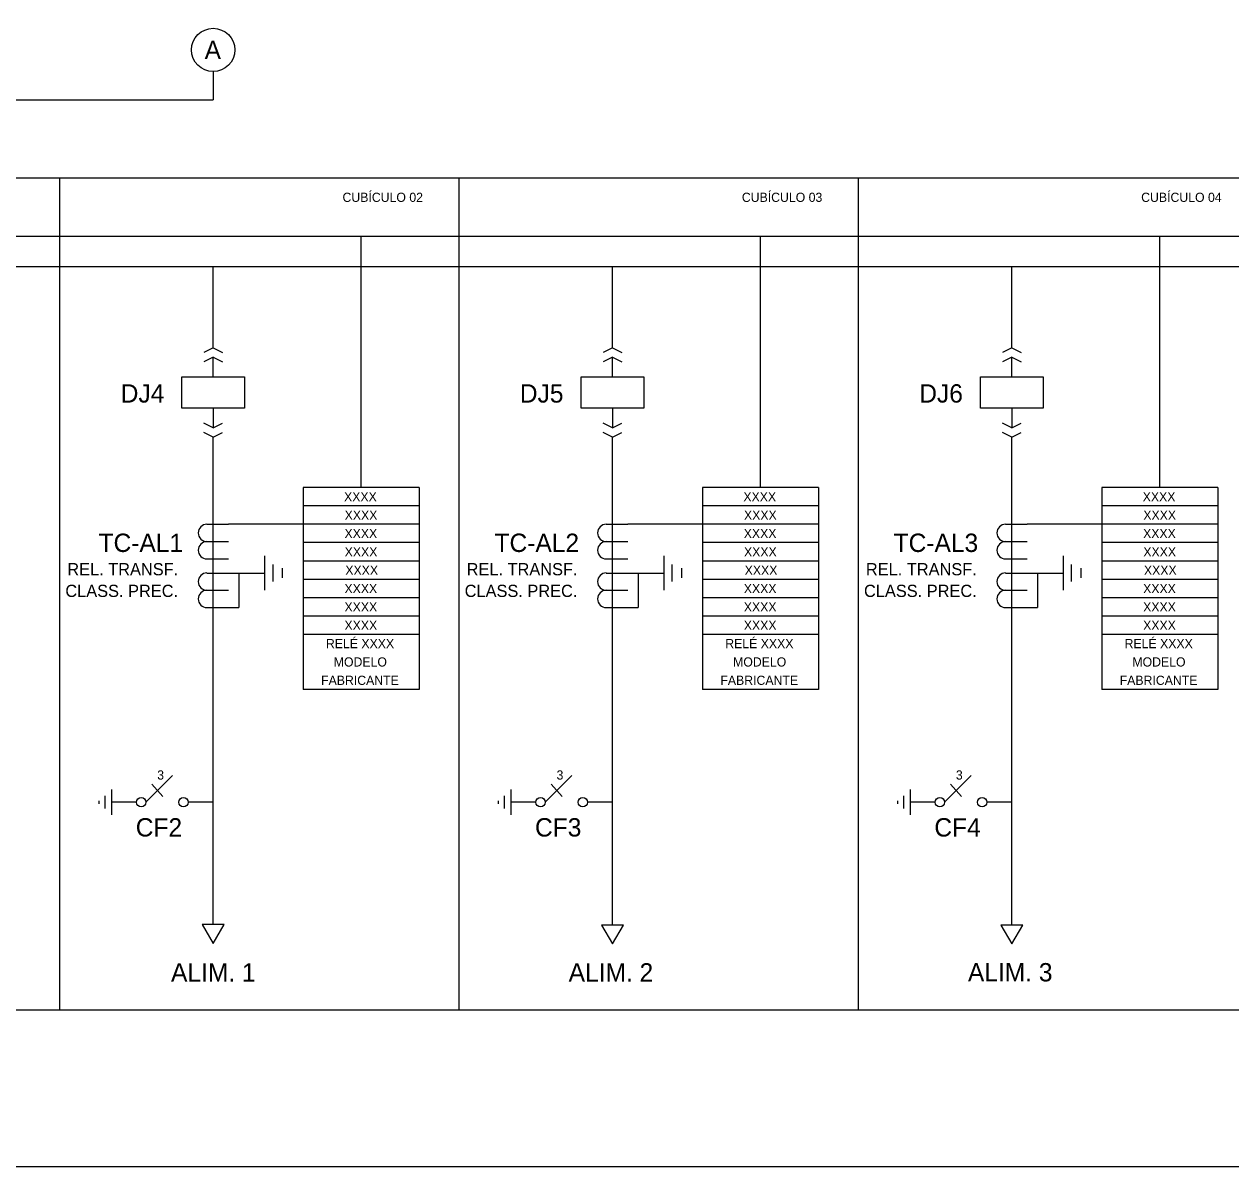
# Model space of a CAD drawing. Extents: x 563 to 1404, y 358 to 952.
# Drawn here: x 768.9 to 966.2, y 561.3 to 748.2 of the extents above; entities that cross this region are included whole.
import ezdxf

# ---------------------------------------------------------------- set-up
doc = ezdxf.new("R2010")
doc.units = 0
doc.layers.add('13', color=7, linetype='Continuous')
doc.layers.add('New Level (0)', color=7, linetype='Continuous')

msp = doc.modelspace()

# ---------------------------------------------------------------- linework, layer by layer
for p, q in [((799.81, 740.38), (799.81, 735.75)), ((650.86, 735.75), (799.81, 735.75)), ((1296.89, 722.95), (622.37, 722.95)), ((774.67, 722.95), (774.67, 586.96)), ((774.67, 722.95), (774.67, 586.96)), ((839.94, 722.95), (839.94, 586.96)), ((839.94, 722.95), (839.94, 586.96)), ((905.22, 722.95), (905.22, 586.96)), ((905.22, 722.95), (905.22, 586.96)), ((1280.96, 713.45), (705.72, 713.45)), ((824.01, 672.38), (824.01, 713.45)), ((889.29, 672.38), (889.29, 713.45)), ((954.57, 672.38), (954.57, 713.45)), ((1256.75, 708.46), (681.52, 708.46)), ((799.81, 695.25), (799.81, 708.46)), ((799.81, 695.25), (799.81, 708.46)), ((865.09, 695.25), (865.09, 708.46)), ((865.09, 695.25), (865.09, 708.46)), ((930.37, 695.25), (930.37, 708.46)), ((930.37, 695.25), (930.37, 708.46)), ((799.81, 690.5), (799.81, 693.73)), ((799.81, 690.5), (799.81, 693.73)), ((865.09, 690.5), (865.09, 693.73)), ((865.09, 690.5), (865.09, 693.73)), ((930.37, 690.5), (930.37, 693.73)), ((930.37, 690.5), (930.37, 693.73)), ((794.69, 685.38), (794.69, 690.5)), ((794.69, 690.5), (804.93, 690.5)), ((804.93, 690.5), (804.93, 685.38)), ((859.97, 685.38), (859.97, 690.5)), ((859.97, 690.5), (870.21, 690.5)), ((870.21, 690.5), (870.21, 685.38)), ((925.24, 685.38), (925.24, 690.5)), ((925.24, 690.5), (935.49, 690.5)), ((935.49, 690.5), (935.49, 685.38)), ((804.93, 685.38), (794.69, 685.38)), ((799.81, 685.38), (799.81, 682.16)), ((870.21, 685.38), (859.97, 685.38)), ((865.09, 685.38), (865.09, 682.16)), ((935.49, 685.38), (925.24, 685.38)), ((930.37, 685.38), (930.37, 682.16)), ((799.81, 600.97), (799.81, 680.63)), ((865.09, 600.87), (865.09, 680.63)), ((930.37, 600.87), (930.37, 680.63)), ((833.5, 672.38), (814.52, 672.38)), ((814.52, 672.38), (814.52, 639.38)), ((833.5, 672.38), (833.5, 639.38)), ((898.78, 672.38), (879.8, 672.38)), ((879.8, 672.38), (879.8, 639.38)), ((898.78, 672.38), (898.78, 639.38)), ((964.06, 672.38), (945.08, 672.38)), ((945.08, 672.38), (945.08, 639.38)), ((964.06, 672.38), (964.06, 639.38)), ((833.5, 669.38), (814.52, 669.38)), ((898.78, 669.38), (879.8, 669.38)), ((964.06, 669.38), (945.08, 669.38)), ((798.79, 666.38), (802.32, 666.38)), ((814.52, 666.38), (802.32, 666.38)), ((833.5, 666.38), (814.52, 666.38)), ((864.06, 666.38), (867.6, 666.38)), ((879.8, 666.38), (867.6, 666.38)), ((898.78, 666.38), (879.8, 666.38)), ((929.34, 666.38), (932.88, 666.38)), ((945.08, 666.38), (932.88, 666.38)), ((964.06, 666.38), (945.08, 666.38)), ((798.79, 663.55), (802.32, 663.55)), ((833.5, 663.38), (814.52, 663.38)), ((864.06, 663.55), (867.6, 663.55)), ((898.78, 663.38), (879.8, 663.38)), ((929.34, 663.55), (932.88, 663.55)), ((964.06, 663.38), (945.08, 663.38)), ((808.19, 661.21), (808.19, 655.63)), ((873.47, 661.21), (873.47, 655.63)), ((938.74, 661.21), (938.74, 655.63)), ((798.79, 660.72), (802.32, 660.72)), ((809.59, 657.02), (809.59, 659.82)), ((811.07, 659.2), (811.07, 657.64)), ((833.5, 660.38), (814.52, 660.38)), ((864.06, 660.72), (867.6, 660.72)), ((874.86, 657.02), (874.86, 659.82)), ((876.34, 659.2), (876.34, 657.64)), ((898.78, 660.38), (879.8, 660.38)), ((929.34, 660.72), (932.88, 660.72)), ((940.14, 657.02), (940.14, 659.82)), ((941.62, 659.2), (941.62, 657.64)), ((964.06, 660.38), (945.08, 660.38)), ((798.79, 658.42), (802.32, 658.42)), ((799.81, 658.42), (808.19, 658.42)), ((833.5, 657.38), (814.52, 657.38)), ((864.06, 658.42), (867.6, 658.42)), ((865.09, 658.42), (873.47, 658.42)), ((898.78, 657.38), (879.8, 657.38)), ((929.34, 658.42), (932.88, 658.42)), ((930.37, 658.42), (938.74, 658.42)), ((964.06, 657.38), (945.08, 657.38)), ((798.79, 655.59), (802.32, 655.59)), ((864.06, 655.59), (867.6, 655.59)), ((929.34, 655.59), (932.88, 655.59)), ((833.5, 654.38), (814.52, 654.38)), ((833.5, 654.38), (814.52, 654.38)), ((898.78, 654.38), (879.8, 654.38)), ((898.78, 654.38), (879.8, 654.38)), ((964.06, 654.38), (945.08, 654.38)), ((964.06, 654.38), (945.08, 654.38)), ((798.79, 652.76), (804, 652.76)), ((833.5, 651.38), (814.52, 651.38)), ((864.06, 652.76), (869.28, 652.76)), ((898.78, 651.38), (879.8, 651.38)), ((929.34, 652.76), (934.55, 652.76)), ((964.06, 651.38), (945.08, 651.38)), ((833.5, 648.38), (814.52, 648.38)), ((898.78, 648.38), (879.8, 648.38)), ((964.06, 648.38), (945.08, 648.38)), ((833.5, 639.38), (814.52, 639.38)), ((898.78, 639.38), (879.8, 639.38)), ((964.06, 639.38), (945.08, 639.38)), ((793.15, 625.29), (788.81, 620.95)), ((789.8, 623.9), (791.6, 621.88)), ((858.43, 625.29), (854.09, 620.95)), ((855.08, 623.9), (856.87, 621.88)), ((923.7, 625.29), (919.36, 620.95)), ((920.35, 623.9), (922.15, 621.88)), ((782.15, 619.93), (782.15, 621.98)), ((783.18, 623), (783.18, 618.91)), ((847.43, 619.93), (847.43, 621.98)), ((848.45, 623), (848.45, 618.91)), ((912.71, 619.93), (912.71, 621.98)), ((913.73, 623), (913.73, 618.91)), ((781.14, 621.19), (781.14, 620.66)), ((787.27, 620.95), (783.18, 620.95)), ((799.81, 620.95), (795.71, 620.95)), ((846.41, 621.19), (846.41, 620.66)), ((852.55, 620.95), (848.45, 620.95)), ((865.09, 620.95), (860.99, 620.95)), ((911.69, 621.19), (911.69, 620.66)), ((917.83, 620.95), (913.73, 620.95)), ((930.37, 620.95), (926.27, 620.95)), ((801.62, 600.97), (798, 600.97)), ((798, 600.97), (799.81, 597.87)), ((801.62, 600.97), (798, 600.97)), ((799.81, 597.87), (801.62, 600.97)), ((866.9, 600.87), (863.28, 600.87)), ((863.28, 600.87), (865.09, 597.77)), ((866.9, 600.87), (863.28, 600.87)), ((865.09, 597.77), (866.9, 600.87)), ((932.18, 600.87), (928.56, 600.87)), ((932.18, 600.87), (928.56, 600.87)), ((928.56, 600.87), (930.37, 597.77)), ((930.37, 597.77), (932.18, 600.87)), ((1296.89, 586.96), (622.37, 586.96))]:
    msp.add_line(p, q)
for centre in [(788.04, 620.95), (794.95, 620.95), (853.32, 620.95), (860.22, 620.95), (918.6, 620.95), (925.5, 620.95)]:
    msp.add_circle(centre, 0.768)
for centre in [(798.79, 664.97), (864.06, 664.97), (929.34, 664.97), (798.79, 662.14), (864.06, 662.14), (929.34, 662.14), (798.79, 657.01), (864.06, 657.01), (929.34, 657.01), (798.79, 654.18), (864.06, 654.18), (929.34, 654.18)]:
    msp.add_arc(centre, 1.42, 90, 270)
at = {"layer": '13'}
for p, q in [((799.81, 695.25), (798.28, 694.49)), ((799.81, 695.25), (801.34, 694.49)), ((865.09, 695.25), (863.56, 694.49)), ((865.09, 695.25), (866.61, 694.49)), ((930.37, 695.25), (928.84, 694.49)), ((930.37, 695.25), (931.89, 694.49)), ((799.81, 693.73), (798.28, 692.97)), ((799.81, 693.73), (801.34, 692.97)), ((865.09, 693.73), (863.56, 692.97)), ((865.09, 693.73), (866.61, 692.97)), ((930.37, 693.73), (928.84, 692.97)), ((930.37, 693.73), (931.89, 692.97)), ((799.81, 682.16), (798.28, 682.92)), ((799.81, 682.16), (801.34, 682.92)), ((865.09, 682.16), (863.56, 682.92)), ((865.09, 682.16), (866.61, 682.92)), ((930.37, 682.16), (928.84, 682.92)), ((930.37, 682.16), (931.89, 682.92)), ((799.81, 680.63), (798.28, 681.4)), ((799.81, 680.63), (801.34, 681.4)), ((865.09, 680.63), (863.56, 681.4)), ((865.09, 680.63), (866.61, 681.4)), ((930.37, 680.63), (928.84, 681.4)), ((930.37, 680.63), (931.89, 681.4))]:
    msp.add_line(p, q, dxfattribs=at)
at = {"layer": 'New Level (0)'}
for p, q in [((804, 658.42), (804, 652.76)), ((869.28, 658.42), (869.28, 652.76)), ((934.55, 658.42), (934.55, 652.76))]:
    msp.add_line(p, q, dxfattribs=at)
msp.add_lwpolyline([(592.61, 760.21), (1379.09, 760.21), (1379.09, 561.33), (592.61, 561.33)], close=True, dxfattribs=at)
msp.add_circle((799.81, 743.93), 3.54, dxfattribs=at)

# ---------------------------------------------------------------- texts
for s, height, p in [('A', 3, (798.41, 742.43)), ('CUBÍCULO 02', 1.5, (820.95, 719.09)), ('CUBÍCULO 03', 1.5, (886.23, 719.09)), ('CUBÍCULO 04', 1.5, (951.51, 719.09)), ('DJ4', 3, (784.69, 686.28)), ('DJ5', 3, (849.94, 686.28)), ('DJ6', 3, (915.23, 686.28)), ('XXXX', 1.5, (821.2, 670.13)), ('XXXX', 1.5, (886.48, 670.13)), ('XXXX', 1.5, (951.76, 670.13)), ('XXXX', 1.5, (821.3, 667.13)), ('XXXX', 1.5, (886.58, 667.13)), ('XXXX', 1.5, (951.86, 667.13)), ('TC-AL1', 3, (781.07, 661.86)), ('XXXX', 1.5, (821.27, 664.13)), ('TC-AL2', 3, (845.8, 661.86)), ('XXXX', 1.5, (886.54, 664.13)), ('TC-AL3', 3, (911.04, 661.86)), ('XXXX', 1.5, (951.82, 664.13)), ('XXXX', 1.5, (821.3, 661.13)), ('XXXX', 1.5, (886.58, 661.13)), ('XXXX', 1.5, (951.86, 661.13)), ('REL. TRANSF.', 2, (775.96, 658.04)), ('XXXX', 1.5, (821.41, 658.13)), ('REL. TRANSF.', 2, (841.24, 658.04)), ('XXXX', 1.5, (886.69, 658.13)), ('REL. TRANSF.', 2, (906.51, 658.04)), ('XXXX', 1.5, (951.96, 658.13)), ('CLASS. PREC.', 2, (775.64, 654.5)), ('XXXX', 1.5, (821.27, 655.13)), ('CLASS. PREC.', 2, (840.92, 654.5)), ('XXXX', 1.5, (886.55, 655.13)), ('CLASS. PREC.', 2, (906.2, 654.5)), ('XXXX', 1.5, (951.83, 655.13)), ('XXXX', 1.5, (821.27, 652.13)), ('XXXX', 1.5, (886.55, 652.13)), ('XXXX', 1.5, (951.83, 652.13)), ('XXXX', 1.5, (821.27, 649.13)), ('XXXX', 1.5, (886.55, 649.13)), ('XXXX', 1.5, (951.83, 649.13)), ('RELÉ XXXX', 1.5, (818.24, 646.13)), ('RELÉ XXXX', 1.5, (883.52, 646.13)), ('RELÉ XXXX', 1.5, (948.8, 646.13)), ('MODELO', 1.5, (819.52, 643.13)), ('MODELO', 1.5, (884.8, 643.13)), ('MODELO', 1.5, (950.07, 643.13)), ('FABRICANTE', 1.5, (817.45, 640.13)), ('FABRICANTE', 1.5, (882.72, 640.13)), ('FABRICANTE', 1.5, (948, 640.13)), ('3', 1.5, (790.66, 624.65)), ('3', 1.5, (855.94, 624.65)), ('3', 1.5, (921.22, 624.65)), ('CF2', 3, (787.15, 615.34)), ('CF3', 3, (852.42, 615.34)), ('CF4', 3, (917.7, 615.34)), ('ALIM. 1', 3, (792.92, 591.63)), ('ALIM. 2', 3, (857.92, 591.63)), ('ALIM. 3', 3, (923.19, 591.65))]:
    msp.add_text(s, height=height).set_placement(p)

doc.saveas('drawing.dxf')
